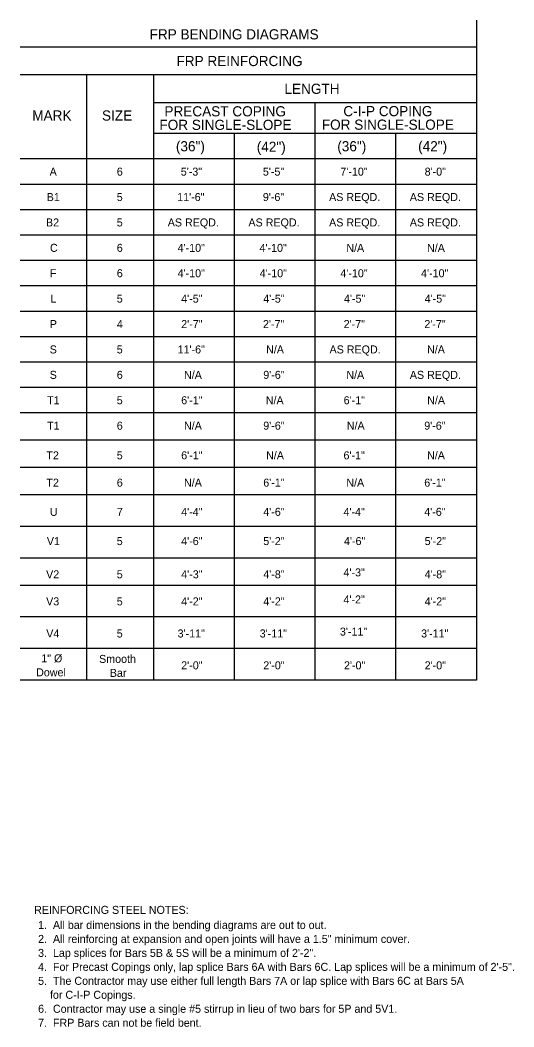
# Model space of a CAD drawing. Extents: x 0 to 4.67, y 0.39 to 9.9.
import ezdxf

# ---------------------------------------------------------------- set-up
doc = ezdxf.new("R2010")
doc.units = 0
for name, color, linetype in [('Border', 7, 'Continuous'), ('Dimension', 7, 'Continuous'), ('TextStructures', 7, 'Continuous')]:
    doc.layers.add(name, color=color, linetype=linetype)

msp = doc.modelspace()

# ---------------------------------------------------------------- linework, layer by layer
at = {"layer": 'Border'}
msp.add_line((4.3111, 9.6449), (0, 9.6449), dxfattribs=at)
at = {"layer": 'Dimension'}
for p, q in [((4.3111, 9.9), (4.3111, 3.6637)), ((4.3111, 9.3825), (0, 9.3825)), ((0.628, 9.3825), (0.628, 3.6637)), ((1.2609, 9.3825), (1.2609, 3.6637)), ((4.3111, 9.1201), (1.2609, 9.1201)), ((2.786, 9.1201), (2.786, 3.6637)), ((4.3111, 8.8285), (1.2609, 8.8285)), ((2.0235, 8.8285), (2.0235, 3.6637)), ((3.5486, 8.8285), (3.5486, 3.6637)), ((4.3111, 8.5885), (0, 8.5885)), ((4.3111, 8.3485), (0, 8.3485)), ((4.3111, 8.1085), (0, 8.1085)), ((4.3111, 7.8685), (0, 7.8685)), ((4.3111, 7.6285), (0, 7.6285)), ((4.3111, 7.3885), (0, 7.3885)), ((4.3111, 7.1485), (0, 7.1485)), ((4.3111, 6.9085), (0, 6.9085)), ((4.3111, 6.6685), (0, 6.6685)), ((4.3111, 6.4285), (0, 6.4285)), ((4.3111, 6.1885), (0, 6.1885)), ((4.3111, 5.9305), (0, 5.9305)), ((4.3111, 5.6725), (0, 5.6725)), ((4.3111, 5.4145), (0, 5.4145)), ((4.3111, 5.116), (0, 5.116)), ((4.3111, 4.8174), (0, 4.8174)), ((4.3111, 4.5594), (0, 4.5594)), ((4.3111, 4.2609), (0, 4.2609)), ((4.3111, 3.9623), (0, 3.9623)), ((4.3111, 3.6637), (0, 3.6637))]:
    msp.add_line(p, q, dxfattribs=at)

# ---------------------------------------------------------------- texts
for s, height, p in [('Smooth', 0.0756, (0.7461, 3.8269)), ('Bar', 0.0756, (0.8474, 3.6949)), ('REINFORCING STEEL NOTES: ', 0.0756, (0.1322, 1.4557)), ('1.  All bar dimensions in the bending diagrams are out to out.', 0.0756, (0.1697, 1.3134)), ('2.  All reinforcing at expansion and open joints will have a 1.5" minimum cover.', 0.0756, (0.1697, 1.1814)), ('3.  Lap splices for Bars 5B & 5S will be a minimum of 2\'-2".', 0.0756, (0.1697, 1.0494)), ('4.  For Precast Copings only, lap splice Bars 6A with Bars 6C. Lap splices will be a minimum of 2\'-5".', 0.0756002, (0.1697, 0.9174)), ('5.  The Contractor may use either full length Bars 7A or lap splice with Bars 6C at Bars 5A', 0.0756, (0.1697, 0.7854)), ('    for C-I-P Copings.', 0.0756, (0.1697, 0.6534)), ('6.  Contractor may use a single #5 stirrup in lieu of two bars for 5P and 5V1.', 0.0756, (0.1697, 0.5214)), ('7.  FRP Bars can not be field bent.', 0.0756, (0.1697, 0.3894))]:
    msp.add_text(s, height=height, dxfattribs=at).set_placement(p)
at = {"layer": 'TextStructures'}
for s, height, p in [('FRP BENDING DIAGRAMS', 0.096, (1.2233, 9.7179)), ('FRP REINFORCING', 0.096, (1.4775, 9.4657)), ('LENGTH', 0.096, (2.4977, 9.2033)), ('MARK', 0.096, (0.1147, 8.9512)), ('SIZE', 0.096, (0.7735, 8.9512)), ('PRECAST COPING', 0.096, (1.3635, 8.9906)), ('C-I-P COPING ', 0.096, (3.0543, 8.9923)), ('FOR SINGLE-SLOPE', 0.096, (1.316, 8.8628)), ('FOR SINGLE-SLOPE', 0.096, (2.8506, 8.8645)), ('(36")', 0.096, (1.472, 8.6606)), ('(42")', 0.096, (2.236, 8.6558)), ('(36")', 0.096, (2.9971, 8.6606)), ('(42")', 0.096, (3.7611, 8.6606)), ('A', 0.0756, (0.2789, 8.4308)), ('6', 0.0756, (0.9136, 8.4308)), ('5\'-3"', 0.0756, (1.5181, 8.4308)), ('5\'-5"', 0.0756, (2.2938, 8.4308)), ('7\'-10"', 0.0756, (3.0262, 8.4308)), ('8\'-0"', 0.0756, (3.8227, 8.4308)), ('B1', 0.0756, (0.2511, 8.1908)), ('5', 0.0756, (0.9131, 8.1908)), ('11\'-6"', 0.0756, (1.4842, 8.1908)), ('9\'-6"', 0.0756, (2.2938, 8.1908)), ('AS REQD.', 0.0756, (2.9199, 8.1908)), ('AS REQD.', 0.0756, (3.6825, 8.1908)), ('B2', 0.0756, (0.2443, 7.9508)), ('5', 0.0756, (0.9131, 7.9508)), ('AS REQD.', 0.0756, (1.3949, 7.9508)), ('AS REQD.', 0.0756, (2.1574, 7.9508)), ('AS REQD.', 0.0756, (2.9199, 7.9508)), ('AS REQD.', 0.0756, (3.6825, 7.9508)), ('C', 0.0756, (0.282, 7.7108)), ('6', 0.0756, (0.9136, 7.7108)), ('4\'-10"', 0.0756, (1.4882, 7.7108)), ('4\'-10"', 0.0756, (2.2623, 7.7108)), ('N/A', 0.0756, (3.0826, 7.7108)), ('N/A', 0.0756, (3.8451, 7.7108)), ('F', 0.0756, (0.2812, 7.4708)), ('6', 0.0756, (0.9136, 7.4708)), ('4\'-10"', 0.0756, (1.4882, 7.4708)), ('4\'-10"', 0.0756, (2.2638, 7.4708)), ('4\'-10"', 0.0756, (3.0263, 7.4708)), ('4\'-10"', 0.0756, (3.7889, 7.4708)), ('L', 0.0756, (0.2875, 7.2308)), ('5', 0.0756, (0.9131, 7.2308)), ('4\'-5"', 0.0756, (1.5221, 7.2308)), ('4\'-5"', 0.0756, (2.2976, 7.2308)), ('4\'-5"', 0.0756, (3.0602, 7.2308)), ('4\'-5"', 0.0756, (3.8227, 7.2308)), ('P', 0.0756, (0.2804, 6.9908)), ('4', 0.0756, (0.9143, 6.9908)), ('2\'-7"', 0.0756, (1.5221, 6.9908)), ('2\'-7"', 0.0756, (2.2948, 6.9908)), ('2\'-7"', 0.0756, (3.0573, 6.9908)), ('2\'-7"', 0.0756, (3.8198, 6.9908)), ('S', 0.0756, (0.2792, 6.7508)), ('5', 0.0756, (0.9131, 6.7508)), ('11\'-6"', 0.0756, (1.4882, 6.7508)), ('N/A', 0.0756, (2.3244, 6.7508)), ('AS REQD.', 0.0756, (2.9239, 6.7508)), ('N/A', 0.0756, (3.8455, 6.7508)), ('S', 0.0756, (0.2792, 6.5108)), ('6', 0.0756, (0.9136, 6.5108)), ('N/A', 0.0756, (1.5488, 6.5108)), ('9\'-6"', 0.0756, (2.2977, 6.5108)), ('N/A', 0.0756, (3.0826, 6.5108)), ('AS REQD.', 0.0756, (3.6825, 6.5108)), ('T1', 0.0756, (0.2549, 6.2708)), ('5', 0.0756, (0.9131, 6.2708)), ('6\'-1"', 0.0756, (1.5221, 6.2708)), ('N/A', 0.0756, (2.3214, 6.2708)), ('6\'-1"', 0.0756, (3.0573, 6.2708)), ('N/A', 0.0756, (3.8465, 6.2708)), ('T1', 0.0756, (0.2549, 6.0308)), ('6', 0.0756, (0.9136, 6.0308)), ('N/A', 0.0756, (1.5488, 6.0308)), ('9\'-6"', 0.0756, (2.2977, 6.0308)), ('N/A', 0.0756, (3.0869, 6.0308)), ('9\'-6"', 0.0756, (3.8189, 6.0308)), ('T2', 0.0756, (0.2481, 5.7503)), ('5', 0.0756, (0.9131, 5.7503)), ('6\'-1"', 0.0756, (1.5221, 5.7503)), ('N/A', 0.0756, (2.3244, 5.7503)), ('6\'-1"', 0.0756, (3.0559, 5.7503)), ('N/A', 0.0756, (3.8455, 5.7503)), ('T2', 0.0756, (0.2481, 5.4923)), ('6', 0.0756, (0.9136, 5.4923)), ('N/A', 0.0756, (1.5488, 5.4923)), ('6\'-1"', 0.0756, (2.2977, 5.4923)), ('N/A', 0.0756, (3.0826, 5.4923)), ('6\'-1"', 0.0756, (3.8189, 5.4923)), ('U', 0.0756, (0.2812, 5.2163)), ('7', 0.0756, (0.9145, 5.2163)), ('4\'-4"', 0.0756, (1.5221, 5.2163)), ('4\'-6"', 0.0756, (2.2977, 5.2163)), ('4\'-4"', 0.0756, (3.0559, 5.2163)), ('4\'-6"', 0.0756, (3.8189, 5.2163)), ('V1', 0.0756, (0.2524, 4.9403)), ('5', 0.0756, (0.9131, 4.9403)), ('4\'-6"', 0.0756, (1.5221, 4.9403)), ('5\'-2"', 0.0756, (2.2977, 4.9403)), ('4\'-6"', 0.0756, (3.0603, 4.9403)), ('5\'-2"', 0.0756, (3.8228, 4.9403)), ('V2', 0.0756, (0.2456, 4.6264)), ('5', 0.0756, (0.9131, 4.6264)), ('4\'-3"', 0.0756, (1.5221, 4.6264)), ('4\'-8"', 0.0756, (2.2977, 4.6264)), ('4\'-3"', 0.0756, (3.0559, 4.6444)), ('4\'-8"', 0.0756, (3.8228, 4.6264)), ('V3', 0.0756, (0.2456, 4.3706)), ('5', 0.0756, (0.9131, 4.3706)), ('4\'-2"', 0.0756, (1.5221, 4.3706)), ('4\'-2"', 0.0756, (2.2977, 4.3706)), ('4\'-2"', 0.0756, (3.0559, 4.3886)), ('4\'-2"', 0.0756, (3.8228, 4.3706)), ('V4', 0.0756, (0.2471, 4.0672)), ('5', 0.0756, (0.9131, 4.0672)), ('3\'-11"', 0.0756, (1.4882, 4.0672)), ('3\'-11"', 0.0756, (2.2638, 4.0672)), ('3\'-11"', 0.0756, (3.022, 4.0852)), ('3\'-11"', 0.0756, (3.7889, 4.0672)), ('1" Ø', 0.0756, (0.1999, 3.8323)), ('2\'-0"', 0.0756, (1.5221, 3.7663)), ('2\'-0"', 0.0756, (2.2977, 3.7663)), ('2\'-0"', 0.0756, (3.0603, 3.7663)), ('2\'-0"', 0.0756, (3.8228, 3.7663)), ('Dowel', 0.0756, (0.1509, 3.7003))]:
    msp.add_text(s, height=height, dxfattribs=at).set_placement(p)

doc.saveas('drawing.dxf')
